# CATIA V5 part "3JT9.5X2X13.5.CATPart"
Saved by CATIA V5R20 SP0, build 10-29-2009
Part number: 3JT9.5X2X13.5
Revision: ANY
Definition: UNKNOWN
Nomenclature: 3JT9.5X2X13.5
Source: Unknown
Bounding box of the stored display mesh (mm): x -6.581 to 6.581, y -1 to 1, z -6.75 to 6.75
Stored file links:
  C:\Users\Utente\Desktop\IO LAVORO\3D X SITO CF\CUMSA\3D files PW\pw081225\pw081225_ejection\3JT9.5X2X13.5.CATPart
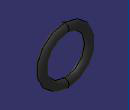
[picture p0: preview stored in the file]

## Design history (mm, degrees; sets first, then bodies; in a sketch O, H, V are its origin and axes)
Body1 "Revolución1" (main body)
  Solid1: solid without history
